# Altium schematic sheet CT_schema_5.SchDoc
size 513 x 378 mm
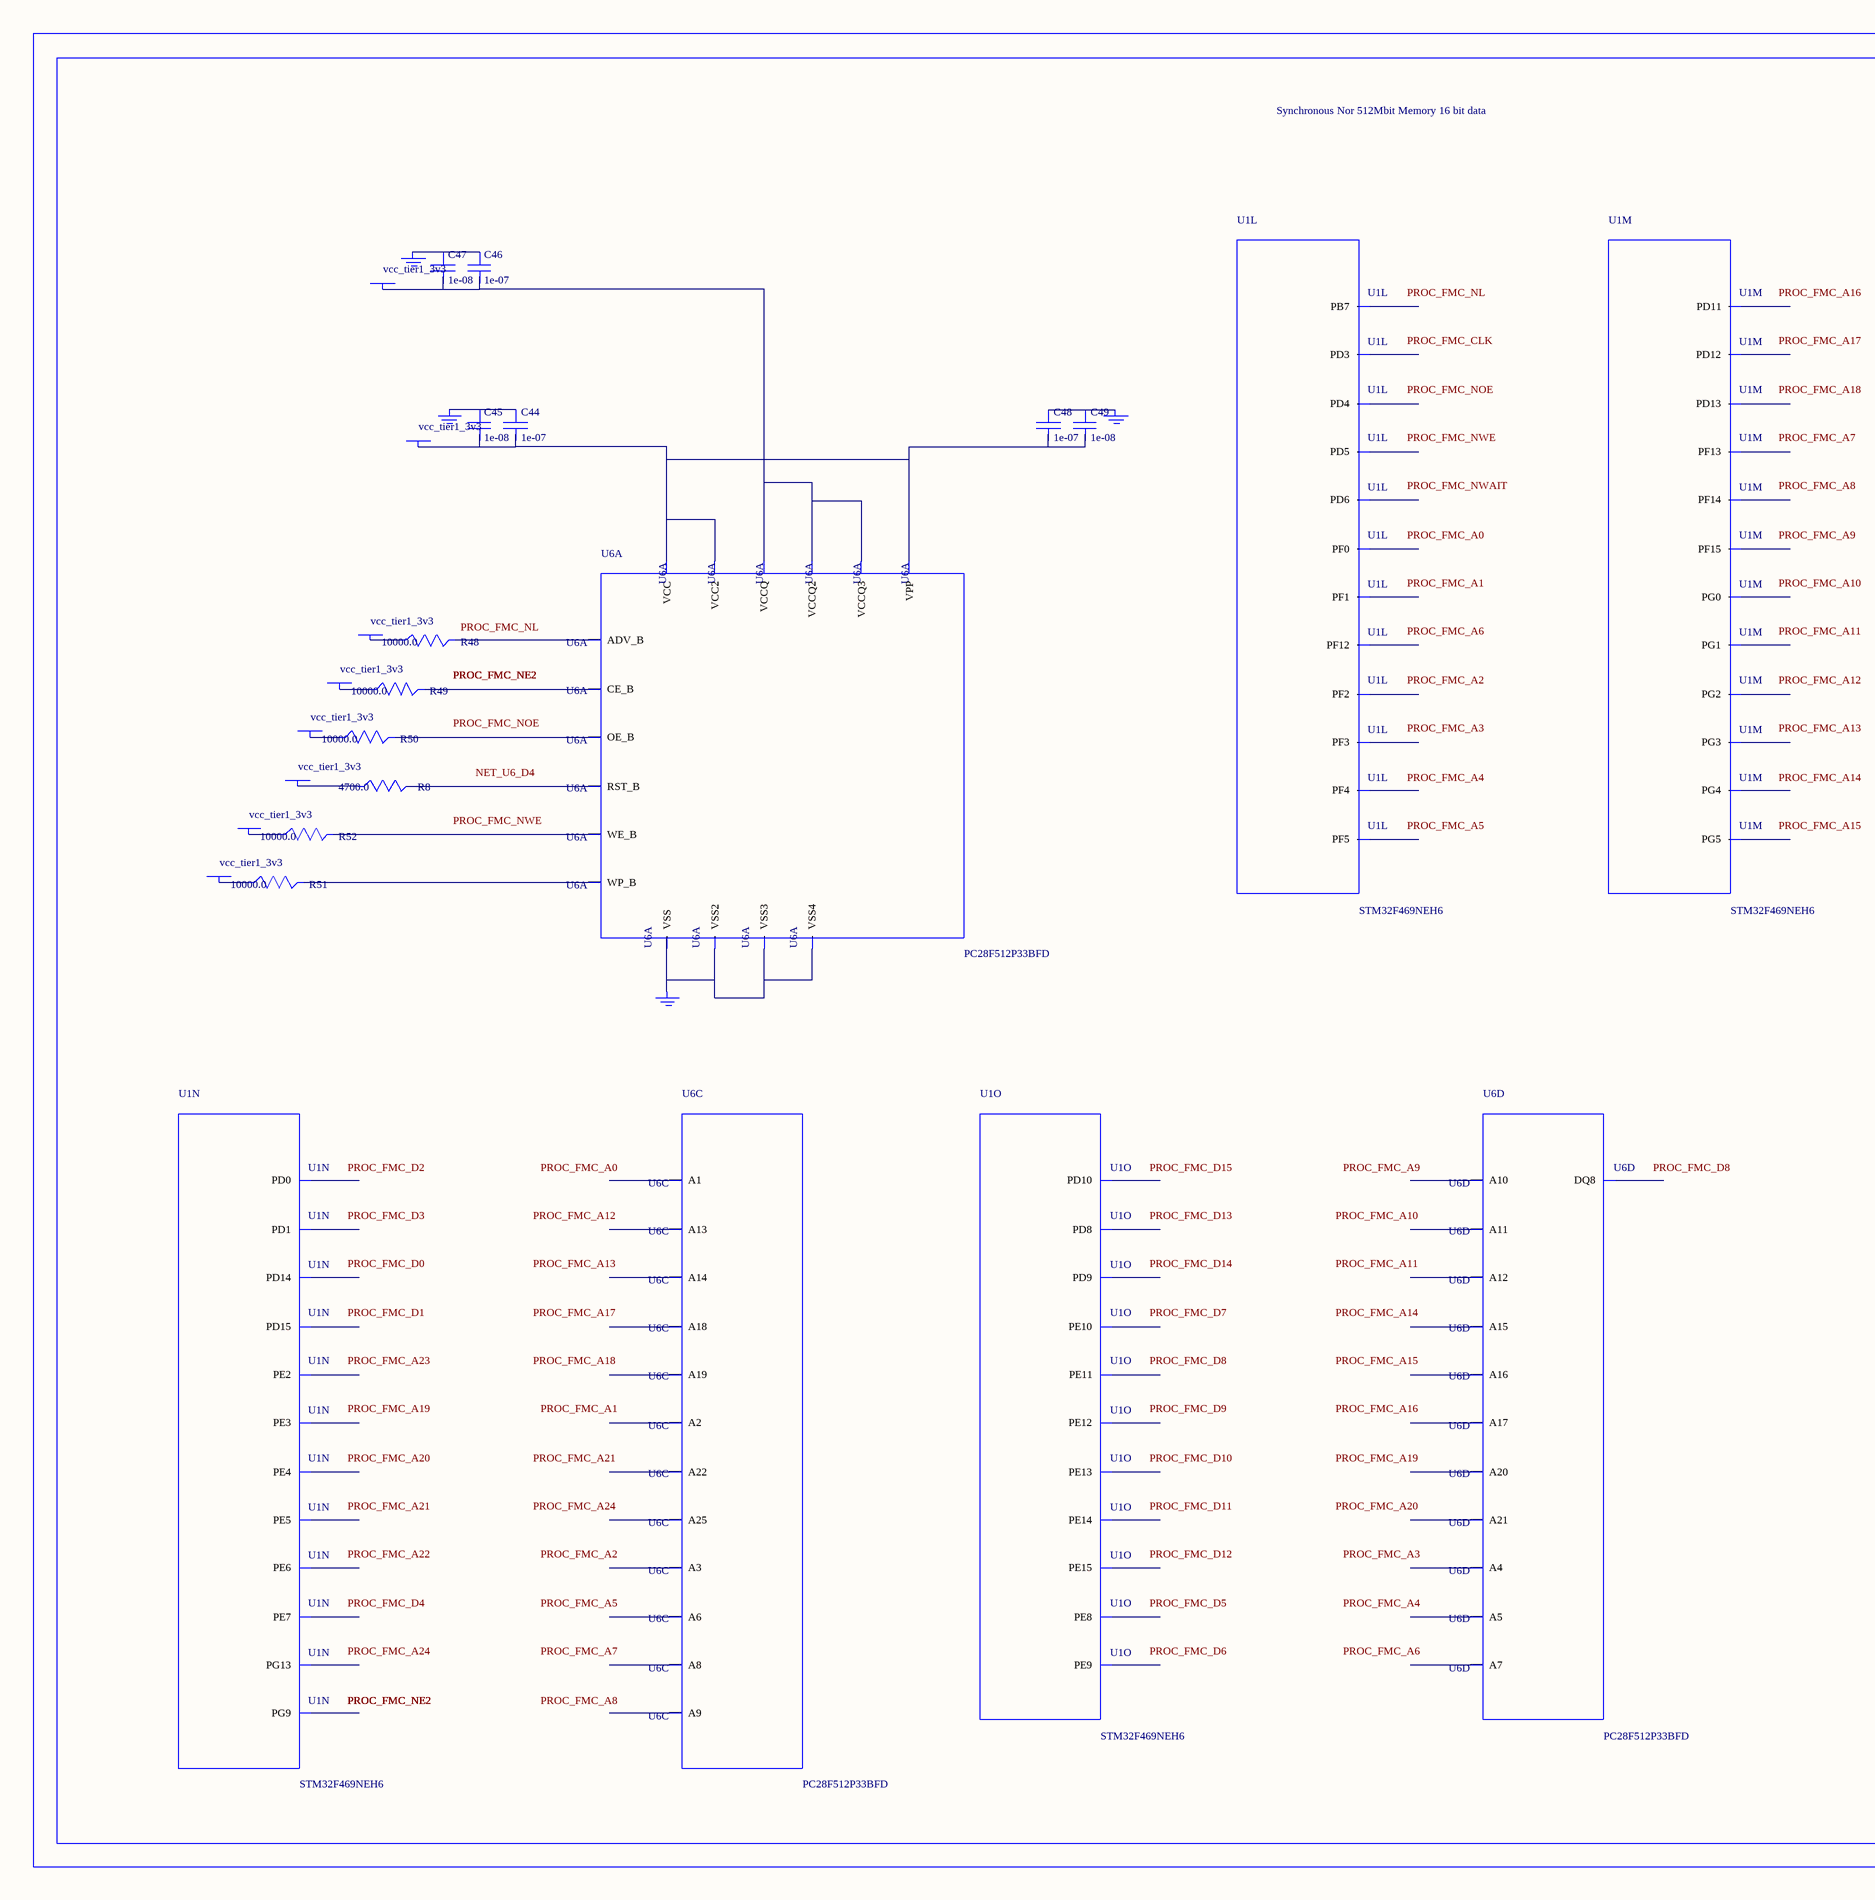
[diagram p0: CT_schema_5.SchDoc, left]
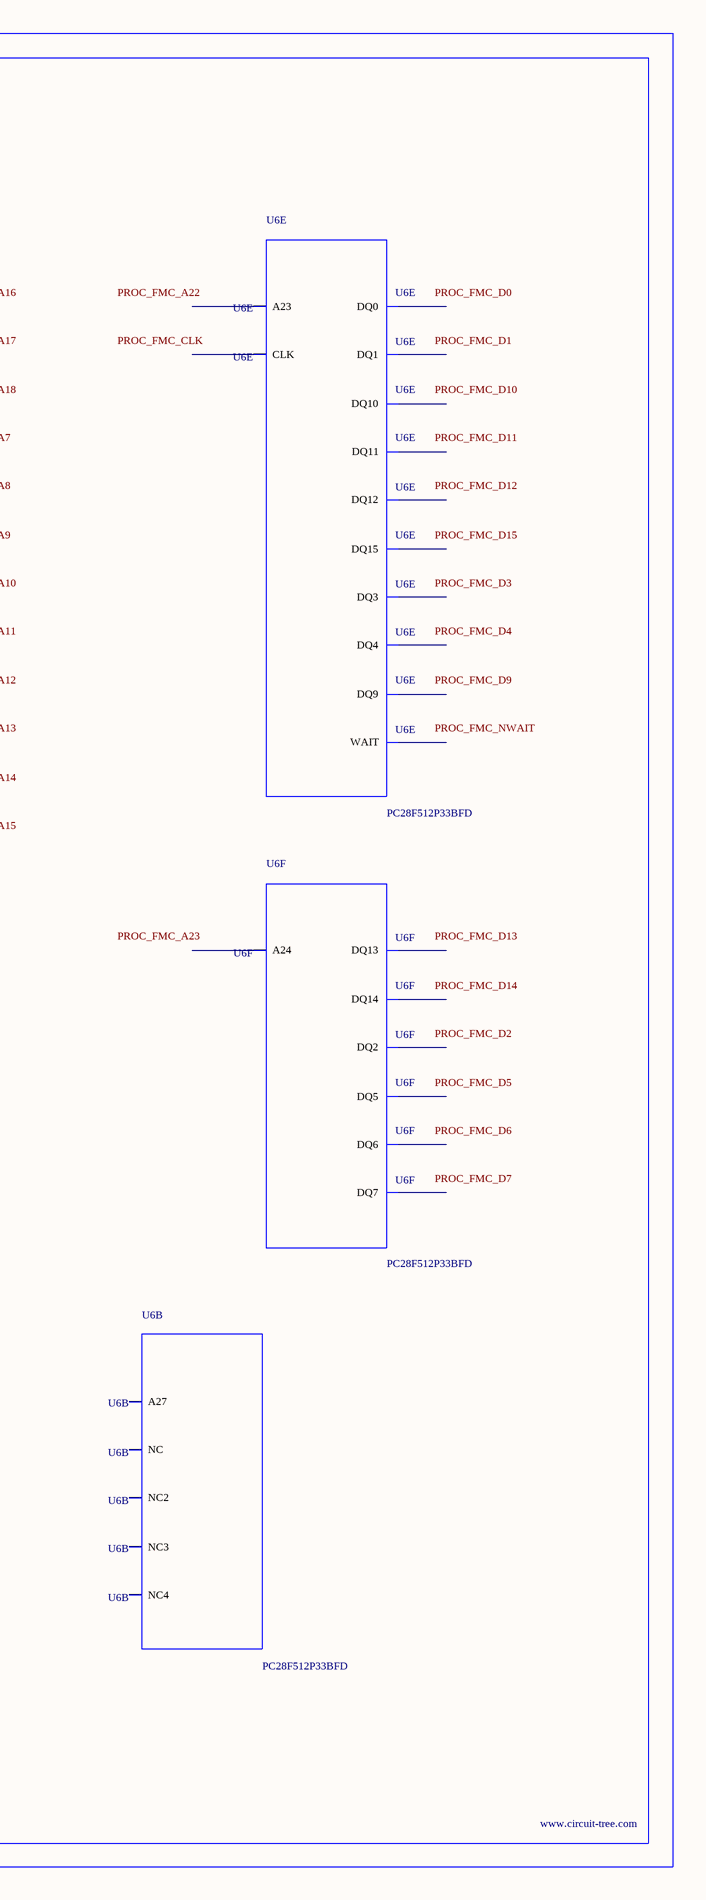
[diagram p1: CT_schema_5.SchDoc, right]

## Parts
BORDER4  (no value)
C44  1e-07  [C0402]
C45  1e-08  [C0402]
C46  1e-07  [C0402]
C47  1e-08  [C0402]
C48  1e-07  [C0402]
C49  1e-08  [C0402]
GND_INSTANCE_4_0  (no value)
GND_INSTANCE_4_1  (no value)
GND_INSTANCE_4_2  (no value)
GND_INSTANCE_4_3  (no value)
POWER_INSTANCE_4_0  vcc_tier1_3v3
POWER_INSTANCE_4_1  vcc_tier1_3v3
POWER_INSTANCE_4_2  vcc_tier1_3v3
POWER_INSTANCE_4_3  vcc_tier1_3v3
POWER_INSTANCE_4_4  vcc_tier1_3v3
POWER_INSTANCE_4_5  vcc_tier1_3v3
POWER_INSTANCE_4_6  vcc_tier1_3v3
POWER_INSTANCE_4_7  vcc_tier1_3v3
R8  4700.0  [R0603]
R48  10000.0  [R0603]
R49  10000.0  [R0603]
R50  10000.0  [R0603]
R51  10000.0  [R0603]
R52  10000.0  [R0603]
U1  STM32F469NEH6  [TFBGA216]  (parts L,M,N,O of 17)
U6  PC28F512P33BFD  [PC28F512P33BFD]  (parts A,B,C,D,E,F of 6)

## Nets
NetC44_1: C44.1 C45.1 GND_INSTANCE_4_0.0(GND)
NetC44_2: C44.2 C45.2 C48.2 C49.2 POWER_INSTANCE_4_0.0(PWR) U6.A4(VPP) U6.A6(VCC) U6.H3(VCC2)
NetC46_1: C46.1 C47.1 GND_INSTANCE_4_1.0(GND)
NetC46_2: C46.2 C47.2 POWER_INSTANCE_4_1.0(PWR) U6.D5(VCCQ) U6.D6(VCCQ2) U6.G4(VCCQ3)
NetC48_1: C48.1 C49.1 GND_INSTANCE_4_2.0(GND)
NetGND_INSTANCE_4_3_0: GND_INSTANCE_4_3.0(GND) U6.B2(VSS) U6.H2(VSS2) U6.H4(VSS3) U6.H6(VSS4)
NetPOWER_INSTANCE_4_2_0: POWER_INSTANCE_4_2.0(PWR) R48.1
NetPOWER_INSTANCE_4_3_0: POWER_INSTANCE_4_3.0(PWR) R49.1
NetPOWER_INSTANCE_4_4_0: POWER_INSTANCE_4_4.0(PWR) R50.1
NetPOWER_INSTANCE_4_5_0: POWER_INSTANCE_4_5.0(PWR) R51.1
NetPOWER_INSTANCE_4_6_0: POWER_INSTANCE_4_6.0(PWR) R52.1
NetPOWER_INSTANCE_4_7_0: POWER_INSTANCE_4_7.0(PWR) R8.1
NetR8_2: R8.2 U6.D4(RST_B)
NetR48_2: R48.2 U6.F6(ADV_B)
NetR49_2: R49.2 U6.B4(CE_B)
NetR50_2: R50.2 U6.F8(OE_B)
NetR51_2: R51.2 U6.C6(WP_B)
NetR52_2: R52.2 U6.G8(WE_B)

Not connected (* = marked no-connect by the designer): U1 A1(PE4) A2(PE3) A3(PE2) B1(PE5) B2(PE6) B3(PG13) B5(PB7) B11(PD6) B12(PD0) C10(PD5) C11(PD3) C12(PD1) D2(PF0) D9(PG9) D11(PD4) E2(PF1) G2(PF2) H2(PF3) J2(PF4) K3(PF5) K13(PD15) K15(PD10) L12(PD14) L14(PD9) L15(PD8) M6(PF12) M7(PG1) M8(PF15) M10(PD12) M11(PD13) M12(PG3) M13(PG2) N6(PF13) N7(PG0) N9(PE8) N10(PD11) N11(PG5) N12(PG4) P6(PF14) P9(PE9) P10(PE11) P11(PE14) R8(PE7) R9(PE10) R10(PE12) R11(PE15) R12(PE13); U6 A1 A2(A6) A3(A8) A5(A13) A7(A18) A8(A22) B1(A2) B3(A9) B5(A14) B6(A25) B7(A19) B8(NC) C1(A3) C2(A7) C3(A10) C4(A12) C5(A15) C7(A20) C8(A21) D1(A4) D2(A5) D3(A11) D7(A16) D8(A17) E1(DQ8) E2(DQ1) E3(DQ9) E4(DQ3) E5(DQ4) E6(CLK) E7(DQ15) E8(NC2) F1(NC3) F2(DQ0) F3(DQ10) F4(DQ11) F5(DQ12) F7(WAIT) G1(A23) G2(NC4) G3(DQ2) G5(DQ5) G6(DQ6) G7(DQ14) H1(A27) H5(DQ13) H7(DQ7) H8(A24)

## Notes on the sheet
- Labels drawn without touching a wire or pin: NET_U6_D4, PROC_FMC_A0, PROC_FMC_A1, PROC_FMC_A2, PROC_FMC_A3, PROC_FMC_A4, PROC_FMC_A5, PROC_FMC_A6, PROC_FMC_A7, PROC_FMC_A8, PROC_FMC_A9, PROC_FMC_A10, PROC_FMC_A11, PROC_FMC_A12, PROC_FMC_A13, PROC_FMC_A14, PROC_FMC_A15, PROC_FMC_A16, PROC_FMC_A17, PROC_FMC_A18, PROC_FMC_A19, PROC_FMC_A20, PROC_FMC_A21, PROC_FMC_A22, PROC_FMC_A23, PROC_FMC_A24, PROC_FMC_CLK, PROC_FMC_D0, PROC_FMC_D1, PROC_FMC_D2, PROC_FMC_D3, PROC_FMC_D4, PROC_FMC_D5, PROC_FMC_D6, PROC_FMC_D7, PROC_FMC_D8, PROC_FMC_D9, PROC_FMC_D10, PROC_FMC_D11, PROC_FMC_D12, PROC_FMC_D13, PROC_FMC_D14, PROC_FMC_D15, PROC_FMC_NL, PROC_FMC_NOE, PROC_FMC_NWAIT, PROC_FMC_NWE

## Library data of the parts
BORDER4 = BORDER_PAGE4
C44 C46 C48 = C0402C104K3RACTU
C45 C47 C49 = C0402C103K3RAC
GND_INSTANCE_4_0-GND_INSTANCE_4_3 = GND
POWER_INSTANCE_4_0-POWER_INSTANCE_4_7 = PWR
R8 = RC0603JR-074K7L
R48-R52 = RC0603JR-0710KL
